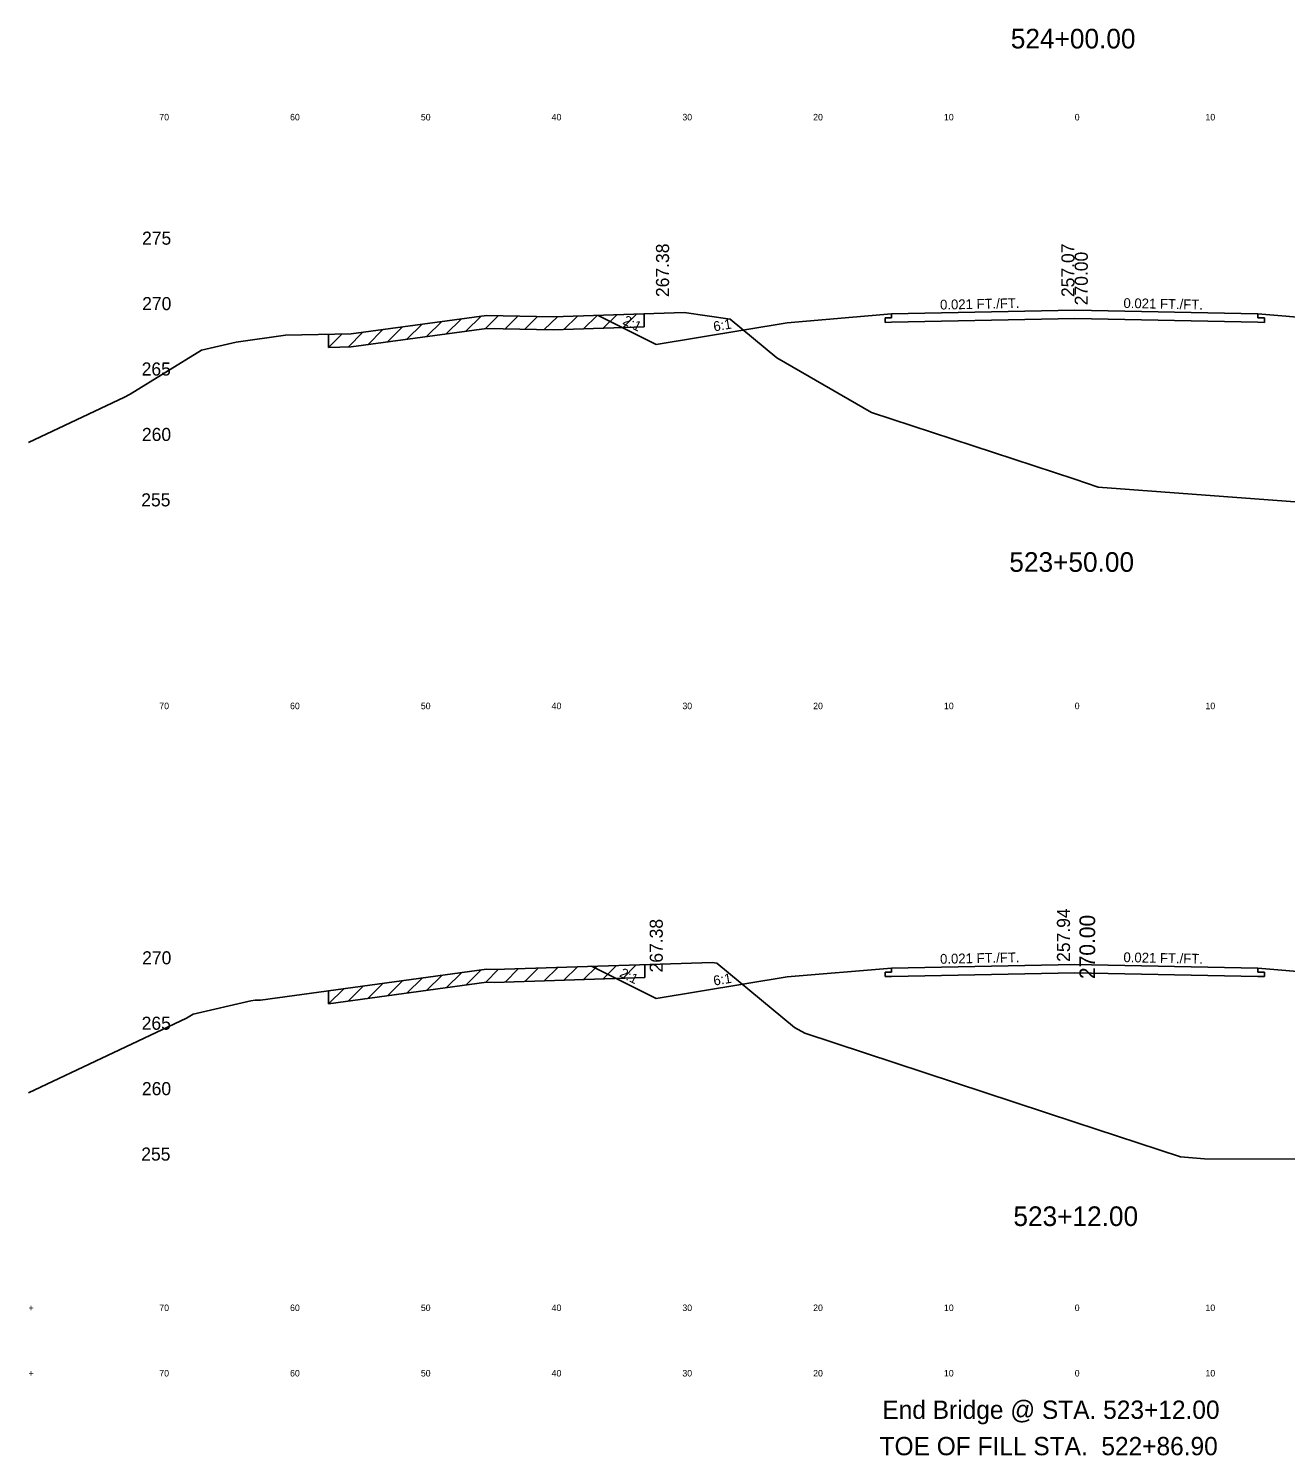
# Model space of a CAD drawing. Extents: x 1000 to 1162, y 999 to 8520.
# Drawn here: x 1000 to 1096.1, y 4162.5 to 4271.5 of the extents above; entities that cross this region are included whole.
import ezdxf

# ---------------------------------------------------------------- set-up
doc = ezdxf.new("R2010")
doc.units = 0
for name, color, linetype in [('Level 10', 7, 'Continuous'), ('Level 11', 7, 'Continuous'), ('Level 12', 7, 'Continuous'), ('Level 20', 7, 'Continuous'), ('Level 3', 7, 'Continuous'), ('Level 32', 7, 'Continuous'), ('Level 33', 7, 'Continuous'), ('Level 56', 7, 'Continuous'), ('Level 59', 7, 'Continuous'), ('Level 6', 7, 'Continuous'), ('Level 60', 7, 'Continuous'), ('Level 61', 7, 'Continuous'), ('Level 7', 7, 'Continuous')]:
    doc.layers.add(name, color=color, linetype=linetype)

msp = doc.modelspace()

# ---------------------------------------------------------------- linework, layer by layer
at = {"layer": 'Level 11'}
for p, q in [((1066, 4249.41), (1065.5, 4249.4)), ((1065.5, 4249.4), (1065.5, 4249.06)), ((1065.5, 4249.06), (1066, 4249.07)), ((1066, 4249.71), (1066, 4249.41)), ((1094, 4249.41), (1094, 4249.71)), ((1094.5, 4249.4), (1094, 4249.41)), ((1094, 4249.07), (1094.5, 4249.06)), ((1094.5, 4249.06), (1094.5, 4249.4)), ((1066, 4199.41), (1065.5, 4199.4)), ((1065.5, 4199.4), (1065.5, 4199.06)), ((1065.5, 4199.06), (1066, 4199.07)), ((1066, 4199.71), (1066, 4199.41)), ((1094, 4199.41), (1094, 4199.71)), ((1094.5, 4199.4), (1094, 4199.41)), ((1094, 4199.07), (1094.5, 4199.06)), ((1094.5, 4199.06), (1094.5, 4199.4))]:
    msp.add_line(p, q, dxfattribs=at)
at = {"layer": 'Level 12'}
for p, q in [((1080, 4249.36), (1066, 4249.07)), ((1094, 4249.07), (1080, 4249.36)), ((1080, 4199.36), (1066, 4199.07)), ((1094, 4199.07), (1080, 4199.36))]:
    msp.add_line(p, q, dxfattribs=at)
at = {"layer": 'Level 59'}
for p, q in [((1066, 4249.71), (1080, 4250)), ((1080, 4250), (1094, 4249.71)), ((1066, 4199.71), (1080, 4200)), ((1080, 4200), (1094, 4199.71))]:
    msp.add_line(p, q, dxfattribs=at)
at = {"layer": 'Level 6'}
for p, q in [((1058, 4249.04), (1066, 4249.71)), ((1094, 4249.71), (1102, 4249.04)), ((1058, 4199.04), (1066, 4199.71)), ((1094, 4199.71), (1102, 4199.04))]:
    msp.add_line(p, q, dxfattribs=at)
at = {"layer": 'Level 60'}
for p, q in [((1024.67, 4248.19), (1035.03, 4249.6)), ((1035.03, 4249.6), (1040.13, 4249.49)), ((1040.13, 4249.49), (1050.13, 4249.82)), ((1050.13, 4249.82), (1053.66, 4249.31)), ((1053.66, 4249.31), (1057.23, 4246.35)), ((1015.89, 4247.56), (1019.65, 4248.09)), ((1019.65, 4248.09), (1024.67, 4248.19)), ((1007.77, 4243.59), (1013.22, 4246.95)), ((1013.22, 4246.95), (1015.89, 4247.56)), ((1057.23, 4246.35), (1064.47, 4242.18)), ((1007.35, 4243.34), (1007.77, 4243.59)), ((1000, 4239.88), (1007.35, 4243.34)), ((1064.47, 4242.18), (1080, 4237.07)), ((1080, 4237.07), (1081.78, 4236.48)), ((1081.78, 4236.48), (1100.68, 4235.05)), ((1035.6, 4199.61), (1052.27, 4200.15)), ((1052.27, 4200.15), (1052.63, 4200.1)), ((1052.63, 4200.1), (1058.57, 4195.18)), ((1017.75, 4197.27), (1035.01, 4199.63)), ((1035.01, 4199.63), (1035.6, 4199.61)), ((1012.58, 4196.2), (1017, 4197.21)), ((1017, 4197.21), (1017.33, 4197.26)), ((1017.33, 4197.26), (1017.75, 4197.27)), ((1000, 4190.19), (1012.08, 4195.89)), ((1012.08, 4195.89), (1012.58, 4196.2)), ((1058.57, 4195.18), (1059.36, 4194.73)), ((1059.36, 4194.73), (1080, 4187.94)), ((1080, 4187.94), (1088.09, 4185.28)), ((1088.09, 4185.28), (1089.92, 4185.14)), ((1089.92, 4185.14), (1110.86, 4185.07))]:
    msp.add_line(p, q, dxfattribs=at)
at = {"layer": 'Level 61'}
for p, q in [((1030.1, 4248.93), (1028.94, 4247.77)), ((1031.6, 4249.13), (1030.44, 4247.98)), ((1033.1, 4249.34), (1031.94, 4248.18)), ((1034.6, 4249.55), (1033.44, 4248.39)), ((1035.93, 4249.58), (1034.94, 4248.59)), ((1037.42, 4249.55), (1036.44, 4248.57)), ((1038.92, 4249.52), (1037.94, 4248.54)), ((1040.44, 4249.5), (1039.44, 4248.51)), ((1041.98, 4249.55), (1040.94, 4248.52)), ((1043.48, 4249.6), (1042.44, 4248.57)), ((1044.98, 4249.65), (1043.94, 4248.62)), ((1046.48, 4249.7), (1045.44, 4248.66)), ((1047.07, 4248.72), (1047.07, 4249.72)), ((1023.96, 4248.17), (1022.94, 4247.15)), ((1022.94, 4248.15), (1022.94, 4247.15)), ((1025.57, 4248.31), (1024.44, 4247.18)), ((1024.67, 4247.19), (1035.03, 4248.6)), ((1027.1, 4248.52), (1025.94, 4247.36)), ((1028.6, 4248.72), (1027.44, 4247.57)), ((1035.03, 4248.6), (1040.13, 4248.49)), ((1040.13, 4248.49), (1047.07, 4248.72)), ((1022.94, 4247.15), (1024.67, 4247.19)), ((1041.97, 4199.82), (1040.94, 4198.79)), ((1043.47, 4199.87), (1042.44, 4198.83)), ((1044.97, 4199.92), (1043.94, 4198.88)), ((1046.47, 4199.97), (1045.44, 4198.93)), ((1047.12, 4198.99), (1047.12, 4199.99)), ((1028.6, 4198.75), (1027.44, 4197.59)), ((1030.1, 4198.95), (1028.94, 4197.8)), ((1031.6, 4199.16), (1030.44, 4198)), ((1033.1, 4199.36), (1031.94, 4198.21)), ((1034.6, 4199.57), (1033.44, 4198.41)), ((1035.95, 4199.63), (1034.94, 4198.62)), ((1035.6, 4198.61), (1047.12, 4198.99)), ((1037.47, 4199.67), (1036.44, 4198.64)), ((1038.97, 4199.72), (1037.94, 4198.69)), ((1040.47, 4199.77), (1039.44, 4198.74)), ((1022.94, 4196.98), (1035.01, 4198.63)), ((1024.1, 4198.13), (1022.94, 4196.98)), ((1022.94, 4197.98), (1022.94, 4196.98)), ((1025.6, 4198.34), (1024.44, 4197.18)), ((1027.1, 4198.54), (1025.94, 4197.39)), ((1035.01, 4198.63), (1035.6, 4198.61))]:
    msp.add_line(p, q, dxfattribs=at)
at = {"layer": 'Level 7'}
for p, q in [((1043.55, 4249.6), (1048, 4247.38)), ((1048, 4247.38), (1058, 4249.04)), ((1043.04, 4199.85), (1048, 4197.38)), ((1048, 4197.38), (1058, 4199.04))]:
    msp.add_line(p, q, dxfattribs=at)

# ---------------------------------------------------------------- texts
at = {"layer": 'Level 10'}
for s, p in [('257.07', (1079.98, 4251)), ('257.94', (1079.64, 4200.19))]:
    msp.add_text(s, height=1, rotation=90, dxfattribs=at).set_placement(p)
at = {"layer": 'Level 11'}
for s, p in [(' 275', (1008.31, 4255)), (' 270', (1008.32, 4250)), (' 265', (1008.28, 4245)), (' 260', (1008.3, 4240)), (' 255', (1008.25, 4235)), (' 270', (1008.32, 4200)), (' 265', (1008.28, 4195)), (' 260', (1008.3, 4190)), (' 255', (1008.25, 4185))]:
    msp.add_text(s, height=1, dxfattribs=at).set_placement(p)
at = {"layer": 'Level 20'}
for s, p in [('End Bridge @ STA. 523+12.00', (1065.29, 4165.26)), ('TOE OF FILL STA.  522+86.90', (1065.08, 4162.48))]:
    msp.add_text(s, height=1.4, dxfattribs=at).set_placement(p)
at = {"layer": 'Level 3'}
for s, p in [('524+00.00', (1075.11, 4270)), ('523+50.00', (1075, 4230)), ('523+12.00', (1075.31, 4180))]:
    msp.add_text(s, height=1.5, dxfattribs=at).set_placement(p)
at = {"layer": 'Level 32'}
for s, rotation, p in [('0.021 FT./FT.', 1.1916, (1069.71, 4250.04)), ('0.021 FT./FT.', 358.8084, (1083.72, 4250.17)), ('2:1', 333.435, (1045.38, 4248.97)), ('6:1', 9.4623, (1052.43, 4248.37)), ('0.021 FT./FT.', 1.1916, (1069.71, 4200.04)), ('0.021 FT./FT.', 358.8084, (1083.72, 4200.17)), ('2:1', 333.435, (1045.13, 4199.09)), ('6:1', 9.4623, (1052.43, 4198.37))]:
    msp.add_text(s, height=0.75, rotation=rotation, dxfattribs=at).set_placement(p)
at = {"layer": 'Level 33'}
for p in [(1048.98, 4251), (1048.5, 4199.38)]:
    msp.add_text('267.38', height=1, rotation=90, dxfattribs=at).set_placement(p)
at = {"layer": 'Level 56'}
for s, p in [('70', (1010, 4264.5)), ('60', (1020, 4264.5)), ('50', (1030, 4264.5)), ('40', (1040, 4264.5)), ('30', (1050, 4264.5)), ('20', (1060, 4264.5)), ('10', (1070, 4264.5)), ('0', (1080, 4264.5)), ('10', (1090, 4264.5)), ('70', (1010, 4219.5)), ('60', (1020, 4219.5)), ('50', (1030, 4219.5)), ('40', (1040, 4219.5)), ('30', (1050, 4219.5)), ('20', (1060, 4219.5)), ('10', (1070, 4219.5)), ('0', (1080, 4219.5)), ('10', (1090, 4219.5)), ('+', (1000, 4173.5)), ('70', (1010, 4173.5)), ('60', (1020, 4173.5)), ('50', (1030, 4173.5)), ('40', (1040, 4173.5)), ('30', (1050, 4173.5)), ('20', (1060, 4173.5)), ('10', (1070, 4173.5)), ('0', (1080, 4173.5)), ('10', (1090, 4173.5)), ('+', (1000, 4168.5)), ('70', (1010, 4168.5)), ('60', (1020, 4168.5)), ('50', (1030, 4168.5)), ('40', (1040, 4168.5)), ('30', (1050, 4168.5)), ('20', (1060, 4168.5)), ('10', (1070, 4168.5)), ('0', (1080, 4168.5)), ('10', (1090, 4168.5))]:
    msp.add_text(s, height=0.5, dxfattribs=at).set_placement(p)
at = {"layer": 'Level 59'}
for height, p in [(1, (1081, 4250)), (1.2, (1081.56, 4198.43))]:
    msp.add_text(' 270.00', height=height, rotation=90, dxfattribs=at).set_placement(p)

doc.saveas('drawing.dxf')
